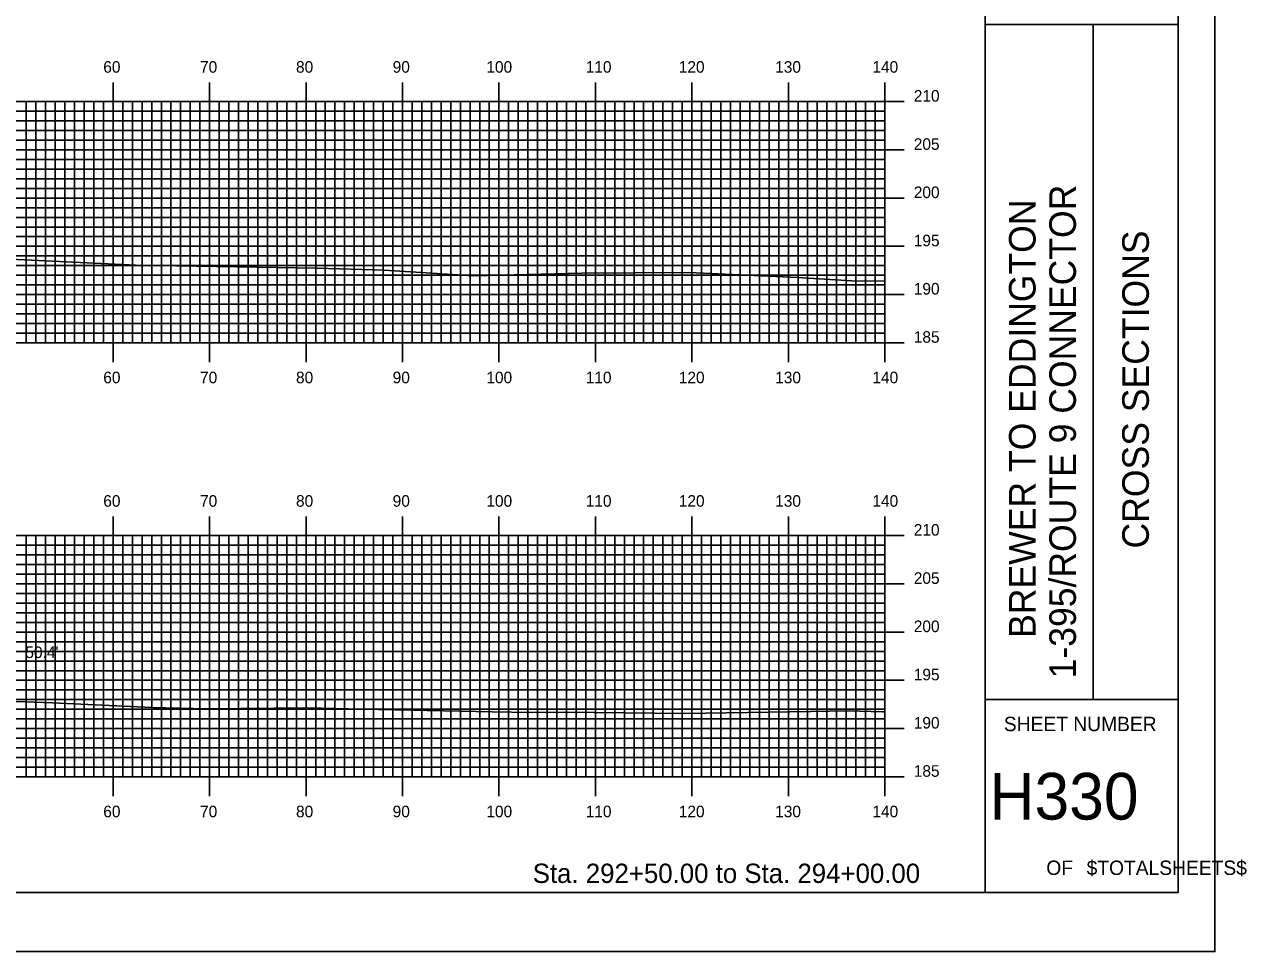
# Model space of a CAD drawing. Extents: x 1814128 to 1814471, y 442591 to 442811.
# Drawn here: x 1814344.8 to 1814471.5, y 442590.5 to 442686.7 of the extents above; entities that cross this region are included whole.
import ezdxf

# ---------------------------------------------------------------- set-up
doc = ezdxf.new("R2010")
doc.units = 0
for name, color, linetype in [('BORDER', 7, 'Continuous'), ('D_Text_Standard', 7, 'Continuous'), ('H_V ANNOTATION', 7, 'Continuous'), ('MAJOR', 7, 'Continuous'), ('MINOR', 7, 'Continuous'), ('PLOT BOUNDARY', 7, 'Continuous'), ('S_Roadway_Centerline', 7, 'Continuous')]:
    doc.layers.add(name, color=color, linetype=linetype)

msp = doc.modelspace()

# ---------------------------------------------------------------- linework, layer by layer
at = {"layer": 'BORDER'}
for p, q in [((1814444.39, 442596.67), (1814444.39, 442806.67)), ((1814444.39, 442686.67), (1814464.39, 442686.67)), ((1814455.58, 442616.67), (1814455.58, 442686.67)), ((1814444.39, 442616.67), (1814464.39, 442616.67))]:
    msp.add_line(p, q, dxfattribs=at)
msp.add_lwpolyline([(1814144.39, 442596.67), (1814464.39, 442596.67), (1814464.39, 442806.67), (1814144.39, 442806.67)], close=True, dxfattribs=at)
at = {"layer": 'MAJOR'}
for p, q in [((1814353.99, 442680.67), (1814353.99, 442678.67)), ((1814363.99, 442680.67), (1814363.99, 442678.67)), ((1814373.99, 442680.67), (1814373.99, 442678.67)), ((1814383.99, 442680.67), (1814383.99, 442678.67)), ((1814393.99, 442680.67), (1814393.99, 442678.67)), ((1814403.99, 442680.67), (1814403.99, 442678.67)), ((1814413.99, 442680.67), (1814413.99, 442678.67)), ((1814423.99, 442680.67), (1814423.99, 442678.67)), ((1814433.99, 442680.67), (1814433.99, 442678.67)), ((1814153.99, 442678.67), (1814433.99, 442678.67)), ((1814153.99, 442678.67), (1814433.99, 442678.67)), ((1814353.99, 442653.67), (1814353.99, 442678.67)), ((1814363.99, 442653.67), (1814363.99, 442678.67)), ((1814373.99, 442653.67), (1814373.99, 442678.67)), ((1814383.99, 442653.67), (1814383.99, 442678.67)), ((1814393.99, 442653.67), (1814393.99, 442678.67)), ((1814403.99, 442653.67), (1814403.99, 442678.67)), ((1814413.99, 442653.67), (1814413.99, 442678.67)), ((1814423.99, 442653.67), (1814423.99, 442678.67)), ((1814436, 442678.67), (1814431.99, 442678.67)), ((1814433.99, 442653.67), (1814433.99, 442678.67)), ((1814433.99, 442653.67), (1814433.99, 442678.67)), ((1814153.99, 442673.67), (1814433.99, 442673.67)), ((1814436, 442673.67), (1814431.99, 442673.67)), ((1814153.99, 442668.67), (1814433.99, 442668.67)), ((1814436, 442668.67), (1814431.99, 442668.67)), ((1814153.99, 442663.67), (1814433.99, 442663.67)), ((1814436, 442663.67), (1814431.99, 442663.67)), ((1814153.99, 442658.67), (1814433.99, 442658.67)), ((1814436, 442658.67), (1814431.99, 442658.67)), ((1814153.99, 442653.67), (1814433.99, 442653.67)), ((1814153.99, 442653.67), (1814433.99, 442653.67)), ((1814353.99, 442651.66), (1814353.99, 442653.67)), ((1814363.99, 442651.66), (1814363.99, 442653.67)), ((1814373.99, 442651.66), (1814373.99, 442653.67)), ((1814383.99, 442651.66), (1814383.99, 442653.67)), ((1814393.99, 442651.66), (1814393.99, 442653.67)), ((1814403.99, 442651.66), (1814403.99, 442653.67)), ((1814413.99, 442651.66), (1814413.99, 442653.67)), ((1814423.99, 442651.66), (1814423.99, 442653.67)), ((1814436, 442653.67), (1814431.99, 442653.67)), ((1814433.99, 442651.66), (1814433.99, 442653.67)), ((1814353.99, 442635.67), (1814353.99, 442633.67)), ((1814363.99, 442635.67), (1814363.99, 442633.67)), ((1814373.99, 442635.67), (1814373.99, 442633.67)), ((1814383.99, 442635.67), (1814383.99, 442633.67)), ((1814393.99, 442635.67), (1814393.99, 442633.67)), ((1814403.99, 442635.67), (1814403.99, 442633.67)), ((1814413.99, 442635.67), (1814413.99, 442633.67)), ((1814423.99, 442635.67), (1814423.99, 442633.67)), ((1814433.99, 442635.67), (1814433.99, 442633.67)), ((1814153.99, 442633.67), (1814433.99, 442633.67)), ((1814153.99, 442633.67), (1814433.99, 442633.67)), ((1814353.99, 442608.67), (1814353.99, 442633.67)), ((1814363.99, 442608.67), (1814363.99, 442633.67)), ((1814373.99, 442608.67), (1814373.99, 442633.67)), ((1814383.99, 442608.67), (1814383.99, 442633.67)), ((1814393.99, 442608.67), (1814393.99, 442633.67)), ((1814403.99, 442608.67), (1814403.99, 442633.67)), ((1814413.99, 442608.67), (1814413.99, 442633.67)), ((1814423.99, 442608.67), (1814423.99, 442633.67)), ((1814436, 442633.67), (1814431.99, 442633.67)), ((1814433.99, 442608.67), (1814433.99, 442633.67)), ((1814433.99, 442608.67), (1814433.99, 442633.67)), ((1814153.99, 442628.67), (1814433.99, 442628.67)), ((1814436, 442628.67), (1814431.99, 442628.67)), ((1814153.99, 442623.67), (1814433.99, 442623.67)), ((1814436, 442623.67), (1814431.99, 442623.67)), ((1814153.99, 442618.67), (1814433.99, 442618.67)), ((1814436, 442618.67), (1814431.99, 442618.67)), ((1814153.99, 442613.67), (1814433.99, 442613.67)), ((1814436, 442613.67), (1814431.99, 442613.67)), ((1814153.99, 442608.67), (1814433.99, 442608.67)), ((1814153.99, 442608.67), (1814433.99, 442608.67)), ((1814353.99, 442606.66), (1814353.99, 442608.67)), ((1814363.99, 442606.66), (1814363.99, 442608.67)), ((1814373.99, 442606.66), (1814373.99, 442608.67)), ((1814383.99, 442606.66), (1814383.99, 442608.67)), ((1814393.99, 442606.66), (1814393.99, 442608.67)), ((1814403.99, 442606.66), (1814403.99, 442608.67)), ((1814413.99, 442606.66), (1814413.99, 442608.67)), ((1814423.99, 442606.66), (1814423.99, 442608.67)), ((1814436, 442608.67), (1814431.99, 442608.67)), ((1814433.99, 442606.66), (1814433.99, 442608.67))]:
    msp.add_line(p, q, dxfattribs=at)
at = {"layer": 'MINOR'}
for p, q in [((1814344.99, 442653.67), (1814344.99, 442678.67)), ((1814345.99, 442653.67), (1814345.99, 442678.67)), ((1814346.99, 442653.67), (1814346.99, 442678.67)), ((1814347.99, 442653.67), (1814347.99, 442678.67)), ((1814348.99, 442653.67), (1814348.99, 442678.67)), ((1814349.99, 442653.67), (1814349.99, 442678.67)), ((1814350.99, 442653.67), (1814350.99, 442678.67)), ((1814351.99, 442653.67), (1814351.99, 442678.67)), ((1814352.99, 442653.67), (1814352.99, 442678.67)), ((1814354.99, 442653.67), (1814354.99, 442678.67)), ((1814355.99, 442653.67), (1814355.99, 442678.67)), ((1814356.99, 442653.67), (1814356.99, 442678.67)), ((1814357.99, 442653.67), (1814357.99, 442678.67)), ((1814358.99, 442653.67), (1814358.99, 442678.67)), ((1814359.99, 442653.67), (1814359.99, 442678.67)), ((1814360.99, 442653.67), (1814360.99, 442678.67)), ((1814361.99, 442653.67), (1814361.99, 442678.67)), ((1814362.99, 442653.67), (1814362.99, 442678.67)), ((1814364.99, 442653.67), (1814364.99, 442678.67)), ((1814365.99, 442653.67), (1814365.99, 442678.67)), ((1814366.99, 442653.67), (1814366.99, 442678.67)), ((1814367.99, 442653.67), (1814367.99, 442678.67)), ((1814368.99, 442653.67), (1814368.99, 442678.67)), ((1814369.99, 442653.67), (1814369.99, 442678.67)), ((1814370.99, 442653.67), (1814370.99, 442678.67)), ((1814371.99, 442653.67), (1814371.99, 442678.67)), ((1814372.99, 442653.67), (1814372.99, 442678.67)), ((1814374.99, 442653.67), (1814374.99, 442678.67)), ((1814375.99, 442653.67), (1814375.99, 442678.67)), ((1814376.99, 442653.67), (1814376.99, 442678.67)), ((1814377.99, 442653.67), (1814377.99, 442678.67)), ((1814378.99, 442653.67), (1814378.99, 442678.67)), ((1814379.99, 442653.67), (1814379.99, 442678.67)), ((1814380.99, 442653.67), (1814380.99, 442678.67)), ((1814381.99, 442653.67), (1814381.99, 442678.67)), ((1814382.99, 442653.67), (1814382.99, 442678.67)), ((1814384.99, 442653.67), (1814384.99, 442678.67)), ((1814385.99, 442653.67), (1814385.99, 442678.67)), ((1814386.99, 442653.67), (1814386.99, 442678.67)), ((1814387.99, 442653.67), (1814387.99, 442678.67)), ((1814388.99, 442653.67), (1814388.99, 442678.67)), ((1814389.99, 442653.67), (1814389.99, 442678.67)), ((1814390.99, 442653.67), (1814390.99, 442678.67)), ((1814391.99, 442653.67), (1814391.99, 442678.67)), ((1814392.99, 442653.67), (1814392.99, 442678.67)), ((1814394.99, 442653.67), (1814394.99, 442678.67)), ((1814395.99, 442653.67), (1814395.99, 442678.67)), ((1814396.99, 442653.67), (1814396.99, 442678.67)), ((1814397.99, 442653.67), (1814397.99, 442678.67)), ((1814398.99, 442653.67), (1814398.99, 442678.67)), ((1814399.99, 442653.67), (1814399.99, 442678.67)), ((1814400.99, 442653.67), (1814400.99, 442678.67)), ((1814401.99, 442653.67), (1814401.99, 442678.67)), ((1814402.99, 442653.67), (1814402.99, 442678.67)), ((1814404.99, 442653.67), (1814404.99, 442678.67)), ((1814405.99, 442653.67), (1814405.99, 442678.67)), ((1814406.99, 442653.67), (1814406.99, 442678.67)), ((1814407.99, 442653.67), (1814407.99, 442678.67)), ((1814408.99, 442653.67), (1814408.99, 442678.67)), ((1814409.99, 442653.67), (1814409.99, 442678.67)), ((1814410.99, 442653.67), (1814410.99, 442678.67)), ((1814411.99, 442653.67), (1814411.99, 442678.67)), ((1814412.99, 442653.67), (1814412.99, 442678.67)), ((1814414.99, 442653.67), (1814414.99, 442678.67)), ((1814415.99, 442653.67), (1814415.99, 442678.67)), ((1814416.99, 442653.67), (1814416.99, 442678.67)), ((1814417.99, 442653.67), (1814417.99, 442678.67)), ((1814418.99, 442653.67), (1814418.99, 442678.67)), ((1814419.99, 442653.67), (1814419.99, 442678.67)), ((1814420.99, 442653.67), (1814420.99, 442678.67)), ((1814421.99, 442653.67), (1814421.99, 442678.67)), ((1814422.99, 442653.67), (1814422.99, 442678.67)), ((1814424.99, 442653.67), (1814424.99, 442678.67)), ((1814425.99, 442653.67), (1814425.99, 442678.67)), ((1814426.99, 442653.67), (1814426.99, 442678.67)), ((1814427.99, 442653.67), (1814427.99, 442678.67)), ((1814428.99, 442653.67), (1814428.99, 442678.67)), ((1814429.99, 442653.67), (1814429.99, 442678.67)), ((1814430.99, 442653.67), (1814430.99, 442678.67)), ((1814431.99, 442653.67), (1814431.99, 442678.67)), ((1814432.99, 442653.67), (1814432.99, 442678.67)), ((1814153.99, 442677.67), (1814433.99, 442677.67)), ((1814433.99, 442677.67), (1814431.99, 442677.67)), ((1814153.99, 442676.67), (1814433.99, 442676.67)), ((1814433.99, 442676.67), (1814431.99, 442676.67)), ((1814153.99, 442675.67), (1814433.99, 442675.67)), ((1814153.99, 442674.67), (1814433.99, 442674.67)), ((1814433.99, 442675.67), (1814431.99, 442675.67)), ((1814433.99, 442674.67), (1814431.99, 442674.67)), ((1814153.99, 442672.67), (1814433.99, 442672.67)), ((1814433.99, 442672.67), (1814431.99, 442672.67)), ((1814153.99, 442671.67), (1814433.99, 442671.67)), ((1814433.99, 442671.67), (1814431.99, 442671.67)), ((1814153.99, 442670.67), (1814433.99, 442670.67)), ((1814153.99, 442669.67), (1814433.99, 442669.67)), ((1814433.99, 442670.67), (1814431.99, 442670.67)), ((1814433.99, 442669.67), (1814431.99, 442669.67)), ((1814153.99, 442667.67), (1814433.99, 442667.67)), ((1814433.99, 442667.67), (1814431.99, 442667.67)), ((1814153.99, 442666.67), (1814433.99, 442666.67)), ((1814433.99, 442666.67), (1814431.99, 442666.67)), ((1814153.99, 442665.67), (1814433.99, 442665.67)), ((1814153.99, 442664.67), (1814433.99, 442664.67)), ((1814433.99, 442665.67), (1814431.99, 442665.67)), ((1814433.99, 442664.67), (1814431.99, 442664.67)), ((1814153.99, 442662.67), (1814433.99, 442662.67)), ((1814433.99, 442662.67), (1814431.99, 442662.67)), ((1814153.99, 442661.67), (1814433.99, 442661.67)), ((1814433.99, 442661.67), (1814431.99, 442661.67)), ((1814153.99, 442660.67), (1814433.99, 442660.67)), ((1814153.99, 442659.67), (1814433.99, 442659.67)), ((1814433.99, 442660.67), (1814431.99, 442660.67)), ((1814433.99, 442659.67), (1814431.99, 442659.67)), ((1814153.99, 442657.67), (1814433.99, 442657.67)), ((1814433.99, 442657.67), (1814431.99, 442657.67)), ((1814153.99, 442656.67), (1814433.99, 442656.67)), ((1814153.99, 442655.67), (1814433.99, 442655.67)), ((1814433.99, 442656.67), (1814431.99, 442656.67)), ((1814433.99, 442655.67), (1814431.99, 442655.67)), ((1814153.99, 442654.67), (1814433.99, 442654.67)), ((1814433.99, 442654.67), (1814431.99, 442654.67)), ((1814344.99, 442608.67), (1814344.99, 442633.67)), ((1814345.99, 442608.67), (1814345.99, 442633.67)), ((1814346.99, 442608.67), (1814346.99, 442633.67)), ((1814347.99, 442608.67), (1814347.99, 442633.67)), ((1814348.99, 442608.67), (1814348.99, 442633.67)), ((1814349.99, 442608.67), (1814349.99, 442633.67)), ((1814350.99, 442608.67), (1814350.99, 442633.67)), ((1814351.99, 442608.67), (1814351.99, 442633.67)), ((1814352.99, 442608.67), (1814352.99, 442633.67)), ((1814354.99, 442608.67), (1814354.99, 442633.67)), ((1814355.99, 442608.67), (1814355.99, 442633.67)), ((1814356.99, 442608.67), (1814356.99, 442633.67)), ((1814357.99, 442608.67), (1814357.99, 442633.67)), ((1814358.99, 442608.67), (1814358.99, 442633.67)), ((1814359.99, 442608.67), (1814359.99, 442633.67)), ((1814360.99, 442608.67), (1814360.99, 442633.67)), ((1814361.99, 442608.67), (1814361.99, 442633.67)), ((1814362.99, 442608.67), (1814362.99, 442633.67)), ((1814364.99, 442608.67), (1814364.99, 442633.67)), ((1814365.99, 442608.67), (1814365.99, 442633.67)), ((1814366.99, 442608.67), (1814366.99, 442633.67)), ((1814367.99, 442608.67), (1814367.99, 442633.67)), ((1814368.99, 442608.67), (1814368.99, 442633.67)), ((1814369.99, 442608.67), (1814369.99, 442633.67)), ((1814370.99, 442608.67), (1814370.99, 442633.67)), ((1814371.99, 442608.67), (1814371.99, 442633.67)), ((1814372.99, 442608.67), (1814372.99, 442633.67)), ((1814374.99, 442608.67), (1814374.99, 442633.67)), ((1814375.99, 442608.67), (1814375.99, 442633.67)), ((1814376.99, 442608.67), (1814376.99, 442633.67)), ((1814377.99, 442608.67), (1814377.99, 442633.67)), ((1814378.99, 442608.67), (1814378.99, 442633.67)), ((1814379.99, 442608.67), (1814379.99, 442633.67)), ((1814380.99, 442608.67), (1814380.99, 442633.67)), ((1814381.99, 442608.67), (1814381.99, 442633.67)), ((1814382.99, 442608.67), (1814382.99, 442633.67)), ((1814384.99, 442608.67), (1814384.99, 442633.67)), ((1814385.99, 442608.67), (1814385.99, 442633.67)), ((1814386.99, 442608.67), (1814386.99, 442633.67)), ((1814387.99, 442608.67), (1814387.99, 442633.67)), ((1814388.99, 442608.67), (1814388.99, 442633.67)), ((1814389.99, 442608.67), (1814389.99, 442633.67)), ((1814390.99, 442608.67), (1814390.99, 442633.67)), ((1814391.99, 442608.67), (1814391.99, 442633.67)), ((1814392.99, 442608.67), (1814392.99, 442633.67)), ((1814394.99, 442608.67), (1814394.99, 442633.67)), ((1814395.99, 442608.67), (1814395.99, 442633.67)), ((1814396.99, 442608.67), (1814396.99, 442633.67)), ((1814397.99, 442608.67), (1814397.99, 442633.67)), ((1814398.99, 442608.67), (1814398.99, 442633.67)), ((1814399.99, 442608.67), (1814399.99, 442633.67)), ((1814400.99, 442608.67), (1814400.99, 442633.67)), ((1814401.99, 442608.67), (1814401.99, 442633.67)), ((1814402.99, 442608.67), (1814402.99, 442633.67)), ((1814404.99, 442608.67), (1814404.99, 442633.67)), ((1814405.99, 442608.67), (1814405.99, 442633.67)), ((1814406.99, 442608.67), (1814406.99, 442633.67)), ((1814407.99, 442608.67), (1814407.99, 442633.67)), ((1814408.99, 442608.67), (1814408.99, 442633.67)), ((1814409.99, 442608.67), (1814409.99, 442633.67)), ((1814410.99, 442608.67), (1814410.99, 442633.67)), ((1814411.99, 442608.67), (1814411.99, 442633.67)), ((1814412.99, 442608.67), (1814412.99, 442633.67)), ((1814414.99, 442608.67), (1814414.99, 442633.67)), ((1814415.99, 442608.67), (1814415.99, 442633.67)), ((1814416.99, 442608.67), (1814416.99, 442633.67)), ((1814417.99, 442608.67), (1814417.99, 442633.67)), ((1814418.99, 442608.67), (1814418.99, 442633.67)), ((1814419.99, 442608.67), (1814419.99, 442633.67)), ((1814420.99, 442608.67), (1814420.99, 442633.67)), ((1814421.99, 442608.67), (1814421.99, 442633.67)), ((1814422.99, 442608.67), (1814422.99, 442633.67)), ((1814424.99, 442608.67), (1814424.99, 442633.67)), ((1814425.99, 442608.67), (1814425.99, 442633.67)), ((1814426.99, 442608.67), (1814426.99, 442633.67)), ((1814427.99, 442608.67), (1814427.99, 442633.67)), ((1814428.99, 442608.67), (1814428.99, 442633.67)), ((1814429.99, 442608.67), (1814429.99, 442633.67)), ((1814430.99, 442608.67), (1814430.99, 442633.67)), ((1814431.99, 442608.67), (1814431.99, 442633.67)), ((1814432.99, 442608.67), (1814432.99, 442633.67)), ((1814153.99, 442632.67), (1814433.99, 442632.67)), ((1814153.99, 442631.67), (1814433.99, 442631.67)), ((1814433.99, 442632.67), (1814431.99, 442632.67)), ((1814433.99, 442631.67), (1814431.99, 442631.67)), ((1814153.99, 442630.67), (1814433.99, 442630.67)), ((1814433.99, 442630.67), (1814431.99, 442630.67)), ((1814153.99, 442629.67), (1814433.99, 442629.67)), ((1814433.99, 442629.67), (1814431.99, 442629.67)), ((1814153.99, 442627.67), (1814433.99, 442627.67)), ((1814153.99, 442626.67), (1814433.99, 442626.67)), ((1814433.99, 442627.67), (1814431.99, 442627.67)), ((1814433.99, 442626.67), (1814431.99, 442626.67)), ((1814153.99, 442625.67), (1814433.99, 442625.67)), ((1814433.99, 442625.67), (1814431.99, 442625.67)), ((1814153.99, 442624.67), (1814433.99, 442624.67)), ((1814433.99, 442624.67), (1814431.99, 442624.67)), ((1814153.99, 442622.67), (1814433.99, 442622.67)), ((1814153.99, 442621.67), (1814433.99, 442621.67)), ((1814433.99, 442622.67), (1814431.99, 442622.67)), ((1814433.99, 442621.67), (1814431.99, 442621.67)), ((1814153.99, 442620.67), (1814433.99, 442620.67)), ((1814433.99, 442620.67), (1814431.99, 442620.67)), ((1814153.99, 442619.67), (1814433.99, 442619.67)), ((1814433.99, 442619.67), (1814431.99, 442619.67)), ((1814153.99, 442617.67), (1814433.99, 442617.67)), ((1814433.99, 442617.67), (1814431.99, 442617.67)), ((1814153.99, 442616.67), (1814433.99, 442616.67)), ((1814433.99, 442616.67), (1814431.99, 442616.67)), ((1814153.99, 442615.67), (1814433.99, 442615.67)), ((1814433.99, 442615.67), (1814431.99, 442615.67)), ((1814153.99, 442614.67), (1814433.99, 442614.67)), ((1814433.99, 442614.67), (1814431.99, 442614.67)), ((1814153.99, 442612.67), (1814433.99, 442612.67)), ((1814433.99, 442612.67), (1814431.99, 442612.67)), ((1814153.99, 442611.67), (1814433.99, 442611.67)), ((1814433.99, 442611.67), (1814431.99, 442611.67)), ((1814153.99, 442610.67), (1814433.99, 442610.67)), ((1814433.99, 442610.67), (1814431.99, 442610.67)), ((1814153.99, 442609.67), (1814433.99, 442609.67)), ((1814433.99, 442609.67), (1814431.99, 442609.67))]:
    msp.add_line(p, q, dxfattribs=at)
at = {"layer": 'PLOT BOUNDARY'}
msp.add_lwpolyline([(1814128.21, 442590.55), (1814468.21, 442590.55), (1814468.21, 442810.55), (1814128.21, 442810.55)], close=True, dxfattribs=at)
at = {"layer": 'S_Roadway_Centerline'}
for points in [[(1814342.63, 442662.38), (1814356.37, 442661.7), (1814375.14, 442661.39), (1814382.08, 442661.19), (1814391.34, 442660.62), (1814402.59, 442660.87), (1814413.67, 442660.94), (1814424.94, 442660.45), (1814430.54, 442660.08), (1814433.99, 442660.05)], [(1814337.24, 442616.72), (1814347.7, 442616.32), (1814357.99, 442615.84), (1814363.79, 442615.72), (1814374.16, 442615.83), (1814379.81, 442615.67), (1814393.28, 442615.42), (1814397.34, 442615.34), (1814400.76, 442615.36), (1814413.24, 442615.23), (1814426.33, 442615.45), (1814430.2, 442615.49), (1814433.74, 442615.39), (1814433.99, 442615.39)]]:
    msp.add_lwpolyline(points, dxfattribs=at)

# ---------------------------------------------------------------- texts
at = {"layer": 'BORDER'}
for s, p in [('1-395/ROUTE 9 CONNECTOR', (1814453.8, 442618.87)), ('BREWER TO EDDINGTON', (1814449.62, 442623.07)), ('CROSS SECTIONS', (1814461.36, 442632.34))]:
    msp.add_text(s, height=2.7557, rotation=90, dxfattribs=at).set_placement(p)
for s, height, p in [('SHEET NUMBER', 1.4905, (1814446.33, 442613.4)), ('H330', 4.839, (1814444.83, 442604.23)), ('OF', 1.491, (1814450.73, 442598.49)), ('$TOTALSHEETS$', 1.4905, (1814454.91, 442598.49))]:
    msp.add_text(s, height=height, dxfattribs=at).set_placement(p)
at = {"layer": 'D_Text_Standard'}
msp.add_text("50.4'", height=1.2, dxfattribs=at).set_placement((1814344.89, 442620.98))
at = {"layer": 'H_V ANNOTATION'}
for s, height, p in [('60', 1.2, (1814352.97, 442681.67)), ('70', 1.2, (1814363, 442681.67)), ('80', 1.2, (1814372.95, 442681.67)), ('90', 1.2, (1814382.97, 442681.67)), ('100', 1.2, (1814392.68, 442681.67)), ('110', 1.2, (1814402.98, 442681.67)), ('120', 1.2, (1814412.63, 442681.67)), ('130', 1.2, (1814422.62, 442681.67)), ('140', 1.2, (1814432.7, 442681.67)), ('210', 1.2, (1814436.99, 442678.67)), ('205', 1.2, (1814436.99, 442673.67)), ('200', 1.2, (1814436.99, 442668.67)), ('195', 1.2, (1814436.99, 442663.67)), ('190', 1.2, (1814436.99, 442658.67)), ('185', 1.2, (1814436.99, 442653.67)), ('60', 1.2, (1814352.97, 442649.47)), ('70', 1.2, (1814363, 442649.47)), ('80', 1.2, (1814372.95, 442649.47)), ('90', 1.2, (1814382.97, 442649.47)), ('100', 1.2, (1814392.68, 442649.47)), ('110', 1.2, (1814402.98, 442649.47)), ('120', 1.2, (1814412.63, 442649.47)), ('130', 1.2, (1814422.62, 442649.47)), ('140', 1.2, (1814432.7, 442649.47)), ('60', 1.2, (1814352.97, 442636.67)), ('70', 1.2, (1814363, 442636.67)), ('80', 1.2, (1814372.95, 442636.67)), ('90', 1.2, (1814382.97, 442636.67)), ('100', 1.2, (1814392.68, 442636.67)), ('110', 1.2, (1814402.98, 442636.67)), ('120', 1.2, (1814412.63, 442636.67)), ('130', 1.2, (1814422.62, 442636.67)), ('140', 1.2, (1814432.7, 442636.67)), ('210', 1.2, (1814436.99, 442633.67)), ('205', 1.2, (1814436.99, 442628.67)), ('200', 1.2, (1814436.99, 442623.67)), ('195', 1.2, (1814436.99, 442618.67)), ('190', 1.2, (1814436.99, 442613.67)), ('185', 1.2, (1814436.99, 442608.67)), ('60', 1.2, (1814352.97, 442604.47)), ('70', 1.2, (1814363, 442604.47)), ('80', 1.2, (1814372.95, 442604.47)), ('90', 1.2, (1814382.97, 442604.47)), ('100', 1.2, (1814392.68, 442604.47)), ('110', 1.2, (1814402.98, 442604.47)), ('120', 1.2, (1814412.63, 442604.47)), ('130', 1.2, (1814422.62, 442604.47)), ('140', 1.2, (1814432.7, 442604.47)), ('Sta. 292+50.00 to Sta. 294+00.00', 2.0004, (1814397.49, 442597.66))]:
    msp.add_text(s, height=height, dxfattribs=at).set_placement(p)

doc.saveas('drawing.dxf')
